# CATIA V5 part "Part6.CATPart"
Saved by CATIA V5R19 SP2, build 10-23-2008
Part number: Part6
Bounding box of the stored display mesh (mm): x -1328.476 to 1950.846, y -752.003 to 751.004, z -1.803 to 1016.571
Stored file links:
  C:\BEHROOZ\catia learning\tarh haye mashin\hb\Part6.CATPart
  C:\BEHROOZ\catia learning\tarh haye mashin\hb\HB.CATPart
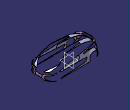
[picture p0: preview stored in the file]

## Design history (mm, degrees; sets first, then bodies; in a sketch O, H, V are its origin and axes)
Body1 (main body)
  DatumSurface1 to DatumSurface10
  Set1
    DatumSurface11 to DatumSurface25
    ThickSurface1: Surface DatumSurface20, TopOffset 1, BotOffset 0
    ThickSurface2: Surface DatumSurface23, TopOffset 1, BotOffset 0
    ThickSurface3: Surface DatumSurface21, TopOffset 1, BotOffset 0
    ThickSurface4: Surface DatumSurface24, TopOffset 1, BotOffset 0
    ThickSurface5: Surface DatumSurface25, TopOffset 1, BotOffset 0
    ThickSurface6: Surface DatumSurface14, TopOffset 1, BotOffset 0
    ThickSurface7: Surface DatumSurface18, TopOffset 1, BotOffset 0
    ThickSurface8: Surface DatumSurface17, TopOffset 1, BotOffset 0
    ThickSurface9: Surface DatumSurface16, TopOffset 1, BotOffset 0
    ThickSurface10: Surface DatumSurface15, TopOffset 1, BotOffset 0
    DatumSurface26 to DatumSurface49
    ThickSurface11: Surface DatumSurface32, TopOffset 1, BotOffset 0
    ThickSurface12: Surface DatumSurface33, TopOffset 1, BotOffset 0
    ThickSurface13: Surface DatumSurface48, TopOffset 1, BotOffset 0
    ThickSurface14: Surface DatumSurface34, TopOffset 1, BotOffset 0
    ThickSurface15: Surface DatumSurface46, TopOffset 1, BotOffset 0
    ThickSurface16: Surface DatumSurface44, TopOffset 1, BotOffset 0
    ThickSurface17: Surface DatumSurface37, TopOffset 1, BotOffset 0
    ThickSurface18: Surface DatumSurface36, TopOffset 1, BotOffset 0
    ThickSurface19: Surface DatumSurface42, TopOffset 1, BotOffset 0
    ThickSurface20: Surface DatumSurface35, TopOffset 1, BotOffset 0
    ThickSurface21: Surface DatumSurface45, TopOffset 1, BotOffset 0
    ThickSurface22: Surface DatumSurface47, TopOffset 1, BotOffset 0
    DatumSurface50
    ThickSurface23: Surface DatumSurface50, TopOffset 1, BotOffset 0
  ThickSurface24: Surface DatumSurface19, TopOffset 1, BotOffset 0
  DatumSurface51
  ThickSurface25: Surface DatumSurface51, TopOffset 1, BotOffset 0
  ThickSurface26: Surface DatumSurface43, TopOffset 1, BotOffset 0
  Plane1: stored without definition
  ThickSurface27: Surface DatumSurface41, TopOffset 1, BotOffset 0
  Sketch1 on Plane1, origin (0, 750, 0), H (-1, 0, 0), V (0, 0, 1)
    arc A1 centre (899.321, -4723.5379) radius 5776.0579 from (-1242.8283, 640.6061) to (-1596.8305, 485.3077) ccw
    point P1 (-1242.8283, 640.6061)
    line L1 (-1232.2579, 671.9845) -> (-1242.8283, 640.6061)
    point P3 (-1242.8283, 640.6061)
    arc A2 centre (-3138.2001, 32.1539) radius 2082.7095 from (-1055.4907, 32.8832) to (-1151.2818, 656.5214) ccw
    point P4 (-1055.4907, 32.8832)
    line L2 (-1055.4907, 32.8832) -> (-177.5083, 73.2965)
    point P6 (-1055.4907, 32.8832)
    point P7 (-177.5083, 73.2965)
    arc A3 centre (-4224.993, 1613.9757) radius 4330.7996 from (-177.5083, 73.2965) to (64.8416, 1019.7164) ccw
    point P8 (-177.5083, 73.2965)
    line L3 (-1232.2579, 671.9845) -> (-1211.7531, 690.7459)
    coincidence: P1 P3, P4 P6, P7 P8
  Pocket1: profile Sketch1, direction (0, -1, 0), length -662, opposite side length -2947, thin wall 1
  ThickSurface28: Surface DatumSurface31, TopOffset 1, BotOffset 0
  Plane2: stored without definition
  ThickSurface29: Surface DatumSurface49, TopOffset 1, BotOffset 0
  Sketch2 on Plane2, origin (0, 0, 449), H (1, 0, 0), V (0, 1, 0)
    unspec C1
    unspec C2
    unspec C3
    unspec C4
    unspec C5
    unspec C6
    unspec C7
    unspec C8
    unspec C9
    line L1 (-1100.042, 0) -> (-1100.0342, 0)
    unspec C10
    unspec C11
    unspec C12
    unspec C13
    unspec C14
    unspec C15
    unspec C16
    unspec C17
    unspec C18
    line L2 (-1201.5247, -0.0086) -> (-1201.5247, 0)
  Pocket2: profile Sketch2, direction (0, 0, -1), length -662, thin wall 1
